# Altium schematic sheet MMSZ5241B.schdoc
size 127 x 101 mm
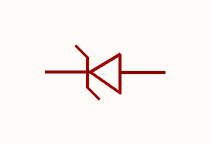
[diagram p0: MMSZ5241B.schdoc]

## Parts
ZD?  mmsz5241b  [SOD-123_L2.8-W1.8-LS3.7-RD]  (value not drawn)

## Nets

Not connected (* = marked no-connect by the designer): ZD? 1(K) 2(A)

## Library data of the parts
ZD? = mmsz5241b: 二极管配置:1个独立式;稳压值(标称值):11V;稳压值(范围):10.45V~11.55V;耗散功率(Pd):350mW;; Manufacturer: CJ(江苏长电/长晶); AddInBom: yes; ModelId: 7884390a25fb4c08947731ebfba7e3f8; ModelTransform: 144.8816,62.992,0,0,0,0,0,0,0; Diode Configuration: 1个独立式; Zener Voltage(Nom): 11V; Reverse Leakage Current (Ir): 2uA; Pd - Power Dissipation: 350mW; Impedance(Zzt): 22Ω; Impedance(Zzk): 600Ω; Operating Junction Temperature Range: -65℃~+150℃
